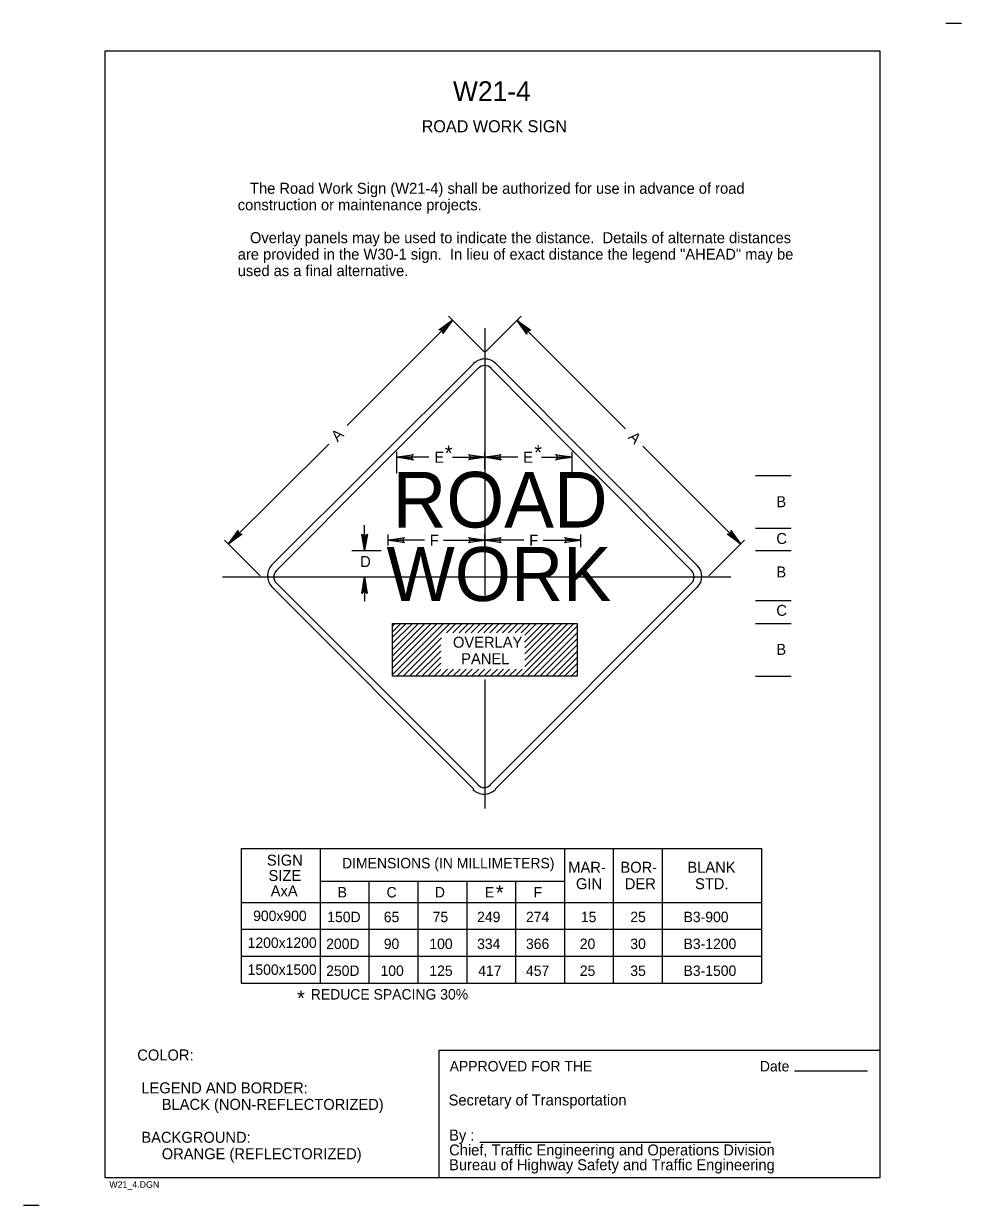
# Model space of a CAD drawing. Extents: x -0.018 to 0.195, y -0.006 to 0.263.
import ezdxf

# ---------------------------------------------------------------- set-up
doc = ezdxf.new("R2010")
doc.units = 0
for name, color, linetype in [('1', 7, 'Continuous'), ('2', 7, 'Continuous'), ('3', 7, 'Continuous')]:
    doc.layers.add(name, color=color, linetype=linetype)

# ---------------------------------------------------------------- blocks, each defined once
blk = doc.blocks.new('RARROW')
at = {"layer": '3'}
for p, q in [((-2.156, 0.28500000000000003), (-2.2665, 0.384625)), ((-2.2665, 0.384625), (0, 0)), ((0, 0), (-2.2665, -0.379125)), ((-2.156, 0.28500000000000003), (-2.075625, 0.12075)), ((0, 0), (-2.156, 0.28500000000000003)), ((-2.14975, -0.2705), (0, 0)), ((-2.075625, 0.12075), (0, 0)), ((0, 0), (-2.074, -0.108)), ((-2.2665, -0.379125), (-2.14975, -0.2705)), ((-2.074, -0.108), (-2.14975, -0.2705))]:
    blk.add_line(p, q, dxfattribs=at)

msp = doc.modelspace()

# ---------------------------------------------------------------- linework, layer by layer
at = {"layer": '1'}
for p, q in [((0.195, 0.26275), (0.1915, 0.26275)), ((0.1765, 0.2565), (0, 0.2565)), ((0, 0.2565), (0, 0)), ((0.1765, 0), (0.1765, 0.2565)), ((0.076, 0.029), (0.1765, 0.029)), ((0.076, 0.029), (0.076, 0)), ((0.157, 0.02425), (0.173625, 0.02425)), ((0.085375, 0.008), (0.151625, 0.008)), ((0, 0), (0.1765, 0)), ((-0.015, -0.0063750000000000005), (-0.0185, -0.0063750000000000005))]:
    msp.add_line(p, q, dxfattribs=at)
at = {"layer": '2'}
msp.add_line((0.1495, 0.074875), (0.1495, 0.0565), dxfattribs=at)
msp.add_line((0.1495, 0.074875), (0.1495, 0.0565), dxfattribs=at)
at = {"layer": '3'}
for p, q in [((0.055125, 0.17125), (0.079125, 0.19525)), ((0.08637500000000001, 0.188), (0.07825, 0.196125)), ((0.08662500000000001, 0.188), (0.09475, 0.196125)), ((0.11850000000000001, 0.1705), (0.093875, 0.195125)), ((0.08650000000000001, 0.193375), (0.08650000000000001, 0.132625)), ((0.038, 0.1395), (0.084, 0.185375)), ((0.039, 0.138125), (0.085, 0.18425)), ((0.08787500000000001, 0.18425), (0.133625, 0.138125)), ((0.089, 0.185375), (0.134875, 0.139375)), ((0.051000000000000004, 0.167), (0.028125, 0.14425)), ((0.0665, 0.160375), (0.0665, 0.16525)), ((0.08650000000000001, 0.16125), (0.08650000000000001, 0.16525)), ((0.106375, 0.16025), (0.106375, 0.16525)), ((0.1225, 0.1665), (0.14475, 0.14425)), ((0.07375, 0.164), (0.0665, 0.164)), ((0.079125, 0.164), (0.08650000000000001, 0.164)), ((0.094, 0.164), (0.08650000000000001, 0.164)), ((0.099375, 0.164), (0.106375, 0.164)), ((0.148125, 0.15987500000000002), (0.15625, 0.15987500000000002)), ((0.059125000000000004, 0.14275000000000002), (0.059125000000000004, 0.1485)), ((0.0645, 0.143875), (0.0645, 0.146375)), ((0.08650000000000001, 0.143125), (0.08650000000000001, 0.146375)), ((0.108375, 0.14350000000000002), (0.108375, 0.146375)), ((0.148125, 0.147875), (0.15625, 0.147875)), ((0.035375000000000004, 0.137), (0.02725, 0.145125)), ((0.05625, 0.14275000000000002), (0.062875, 0.14275000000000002)), ((0.07275, 0.145125), (0.0645, 0.145125)), ((0.077125, 0.145125), (0.08650000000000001, 0.145125)), ((0.095375, 0.145125), (0.08650000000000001, 0.145125)), ((0.09975, 0.145125), (0.108375, 0.145125)), ((0.1375, 0.137), (0.145625, 0.145125)), ((0.148125, 0.14275000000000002), (0.15625, 0.14275000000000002)), ((0.02675, 0.13675), (0.14250000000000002, 0.13675)), ((0.085, 0.089375), (0.039, 0.135375)), ((0.059125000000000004, 0.13675), (0.059125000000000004, 0.13125)), ((0.133625, 0.135375), (0.08775000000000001, 0.089375)), ((0.038, 0.1345), (0.084, 0.088375)), ((0.088875, 0.088375), (0.134875, 0.134375)), ((0.148125, 0.131375), (0.15625, 0.131375)), ((0.0655, 0.123), (0.068625, 0.12612500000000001)), ((0.0655, 0.121625), (0.07, 0.12612500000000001)), ((0.0655, 0.12025), (0.07137500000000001, 0.12612500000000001)), ((0.0655, 0.11875000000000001), (0.072875, 0.12612500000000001)), ((0.0655, 0.11737500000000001), (0.07425, 0.12612500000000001)), ((0.0655, 0.116), (0.075625, 0.12612500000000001)), ((0.0655, 0.1145), (0.077125, 0.12612500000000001)), ((0.0655, 0.12425), (0.067375, 0.12612500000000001)), ((0.0655, 0.1255), (0.066125, 0.12612500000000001)), ((0.0665, 0.114125), (0.0785, 0.12612500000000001)), ((0.07775, 0.124), (0.079875, 0.12612500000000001)), ((0.07925, 0.124), (0.081375, 0.12612500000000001)), ((0.080625, 0.124), (0.08275, 0.12612500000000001)), ((0.082, 0.124), (0.084125, 0.12612500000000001)), ((0.083375, 0.124), (0.0855, 0.12612500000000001)), ((0.084875, 0.124), (0.08700000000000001, 0.12612500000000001)), ((0.08625000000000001, 0.124), (0.088375, 0.12612500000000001)), ((0.08762500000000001, 0.124), (0.08975, 0.12612500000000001)), ((0.089125, 0.124), (0.09125, 0.12612500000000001)), ((0.0905, 0.124), (0.092625, 0.12612500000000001)), ((0.091875, 0.124), (0.094, 0.12612500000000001)), ((0.093375, 0.124), (0.0955, 0.12612500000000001)), ((0.09475, 0.124), (0.096875, 0.12612500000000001)), ((0.0955, 0.121875), (0.09975, 0.12612500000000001)), ((0.095625, 0.120625), (0.101125, 0.12612500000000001)), ((0.095625, 0.11925000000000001), (0.10250000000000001, 0.12612500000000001)), ((0.095625, 0.11775000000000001), (0.10400000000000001, 0.12612500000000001)), ((0.095625, 0.116375), (0.105375, 0.12612500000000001)), ((0.095625, 0.115), (0.10675, 0.12612500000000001)), ((0.095625, 0.1235), (0.09825, 0.12612500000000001)), ((0.096125, 0.114125), (0.1075, 0.1255)), ((0.097625, 0.114125), (0.1075, 0.124)), ((0.148125, 0.12612500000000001), (0.15625, 0.12612500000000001)), ((0.067875, 0.114125), (0.076625, 0.122875)), ((0.069375, 0.114125), (0.0765, 0.12125)), ((0.099, 0.114125), (0.1075, 0.122625)), ((0.100375, 0.114125), (0.1075, 0.12125)), ((0.07075000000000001, 0.114125), (0.0765, 0.11987500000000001)), ((0.072125, 0.114125), (0.0765, 0.11850000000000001)), ((0.10187500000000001, 0.114125), (0.1075, 0.11975000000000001)), ((0.0735, 0.114125), (0.0765, 0.117125)), ((0.076375, 0.114125), (0.078, 0.11575)), ((0.07775, 0.114125), (0.079375, 0.11575)), ((0.07925, 0.114125), (0.080875, 0.11575)), ((0.080625, 0.114125), (0.08225, 0.11575)), ((0.082, 0.114125), (0.083625, 0.11575)), ((0.0835, 0.114125), (0.085125, 0.11575)), ((0.084875, 0.114125), (0.08650000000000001, 0.11575)), ((0.08625000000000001, 0.114125), (0.08787500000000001, 0.11575)), ((0.08775000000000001, 0.114125), (0.089375, 0.11575)), ((0.089125, 0.114125), (0.09075, 0.11575)), ((0.0905, 0.114125), (0.092125, 0.11575)), ((0.092, 0.114125), (0.093625, 0.11575)), ((0.093375, 0.114125), (0.095, 0.11575)), ((0.10325000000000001, 0.114125), (0.1075, 0.11837500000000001)), ((0.104625, 0.114125), (0.1075, 0.117)), ((0.075, 0.114125), (0.0765, 0.115625)), ((0.08650000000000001, 0.113375), (0.08650000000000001, 0.084)), ((0.09475, 0.114125), (0.0955, 0.114875)), ((0.106125, 0.114125), (0.1075, 0.1155)), ((0.148125, 0.114125), (0.15625, 0.114125)), ((0.031, 0.074875), (0.031, 0.04425)), ((0.031, 0.074875), (0.1495, 0.074875)), ((0.049, 0.074875), (0.049, 0.04425)), ((0.104625, 0.067375), (0.049, 0.067375)), ((0.031, 0.062625), (0.1495, 0.062625)), ((0.031, 0.0565), (0.1495, 0.0565)), ((0.031, 0.050375), (0.1495, 0.050375)), ((0.031, 0.04425), (0.1495, 0.04425))]:
    msp.add_line(p, q, dxfattribs=at)
msp.add_lwpolyline([(0.0655, 0.12612500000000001), (0.1075, 0.12612500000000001), (0.1075, 0.114125), (0.0655, 0.114125)], close=True, dxfattribs=at)
for points in [[(0.104625, 0.074875), (0.104625, 0.04425)], [(0.11575, 0.074875), (0.11575, 0.04425)], [(0.12687500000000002, 0.074875), (0.12687500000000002, 0.04425)], [(0.1495, 0.074875), (0.1495, 0.04425)], [(0.1495, 0.074875), (0.1495, 0.0565)], [(0.060125, 0.067375), (0.060125, 0.04425)], [(0.07125000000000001, 0.067375), (0.07125000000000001, 0.04425)], [(0.082375, 0.067375), (0.082375, 0.04425)], [(0.0935, 0.067375), (0.0935, 0.04425)]]:
    msp.add_lwpolyline(points, dxfattribs=at)
for centre, radius, start, end in [((0.08649708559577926, 0.1828493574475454), 0.003535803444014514, 44.92397500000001, 135.85339444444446), ((0.08649708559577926, 0.1828493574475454), 0.0020204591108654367, 44.92397500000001, 135.85339444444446), ((0.040538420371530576, 0.13701110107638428), 0.003535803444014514, 135.70475555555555, 224.93711944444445), ((0.04048239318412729, 0.13674931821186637), 0.00202, 135.04750833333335, 225.00000000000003), ((0.13214328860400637, 0.13675), 0.00202, 315, 45), ((0.13236868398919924, 0.136875), 0.00354, 315, 45), ((0.0863511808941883, 0.09079999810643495), 0.0020204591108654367, 223.5818638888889, 316.1202777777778), ((0.0863511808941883, 0.09079999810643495), 0.0035358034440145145, 223.5818638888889, 316.1202777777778)]:
    msp.add_arc(centre, radius, start, end, dxfattribs=at)

# ---------------------------------------------------------------- block references
for p, xscale, yscale, rotation in [((0.079125, 0.19525), 0.0016545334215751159, 0.0016366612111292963, 45.00000000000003), ((0.093875, 0.195125), 0.001654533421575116, 0.001636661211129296, 135), ((0.0665, 0.164), 0.0016545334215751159, 0.0016366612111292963, 180), ((0.08650000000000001, 0.164), 0.0016545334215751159, 0.0016366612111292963, 180), ((0.028125, 0.14425), 0.0016545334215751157, 0.001636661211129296, -135), ((0.059125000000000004, 0.14275000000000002), 0.0016545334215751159, 0.0016366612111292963, -90), ((0.0645, 0.145125), 0.0016545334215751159, 0.0016366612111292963, 180), ((0.08650000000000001, 0.145125), 0.0016545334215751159, 0.0016366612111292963, 180), ((0.14475, 0.14425), 0.0016545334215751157, 0.001636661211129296, -45), ((0.059125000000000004, 0.13675), 0.0016545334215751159, 0.0016366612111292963, 90)]:
    msp.add_blockref('RARROW', p, dxfattribs=dict(at, xscale=xscale, yscale=yscale, rotation=rotation))
at = {"layer": '3', "xscale": 0.0016545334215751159, "yscale": 0.0016366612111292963}
for p in [(0.08650000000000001, 0.164), (0.106375, 0.164), (0.08650000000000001, 0.145125), (0.108375, 0.145125)]:
    msp.add_blockref('RARROW', p, dxfattribs=at)

# ---------------------------------------------------------------- texts
at = {"layer": '1'}
for s, height, p in [('W21-4', 0.0045000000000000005, (0.07925, 0.245125)), ('ROAD WORK SIGN', 0.00275025, (0.072125, 0.23800000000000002)), ('COLOR:', 0.0024997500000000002, (0.0073750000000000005, 0.026625)), ('APPROVED FOR THE', 0.0023752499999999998, (0.0785, 0.024125)), ('Date ', 0.0023752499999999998, (0.149125, 0.024125)), (' LEGEND AND BORDER:', 0.0024997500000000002, (0.0073750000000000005, 0.019125)), ('Secretary of Transportation', 0.0024997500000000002, (0.07825, 0.016375)), ('      BLACK (NON-REFLECTORIZED)', 0.0024997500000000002, (0.0073750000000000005, 0.015375)), ('By :', 0.0024997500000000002, (0.078375, 0.008375)), (' BACKGROUND:', 0.0024997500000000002, (0.0073750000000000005, 0.007875)), ('      ORANGE (REFLECTORIZED)', 0.0024997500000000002, (0.0073750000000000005, 0.004125)), ('Chief, Traffic Engineering and Operations Division', 0.0024997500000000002, (0.078375, 0.005)), ('Bureau of Highway Safety and Traffic Engineering', 0.0024997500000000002, (0.078375, 0.0016250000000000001)), ('W21_4.DGN', 0.0015, (0.001, -0.002375))]:
    msp.add_text(s, height=height, dxfattribs=at).set_placement(p)
at = {"layer": '2'}
for s, p in [('   The Road Work Sign (W21-4) shall be authorized for use in advance of road ', (0.03025, 0.224)), ('construction or maintenance projects.', (0.03025, 0.22025)), ('   Overlay panels may be used to indicate the distance.  Details of alternate distances ', (0.03025, 0.21275)), ('are provided in the W30-1 sign.  In lieu of exact distance the legend "AHEAD" may be', (0.03025, 0.209)), ('used as a final alternative.', (0.03025, 0.20525000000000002))]:
    msp.add_text(s, height=0.0024997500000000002, dxfattribs=at).set_placement(p)
at = {"layer": '3'}
for rotation, p in [(45, (0.053, 0.167375)), (315, (0.11900000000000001, 0.168375))]:
    msp.add_text('A', height=0.0024997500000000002, rotation=rotation, dxfattribs=at).set_placement(p)
for s, height, p in [('E', 0.0024997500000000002, (0.075, 0.16275)), ('*', 0.00342, (0.077375, 0.16325)), ('E', 0.0024997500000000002, (0.09525, 0.16275)), ('*', 0.00342, (0.09775, 0.163375)), ('ROAD', 0.0126735, (0.0655, 0.148)), ('B', 0.0024997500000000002, (0.152875, 0.152625)), ('F', 0.0024997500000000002, (0.074, 0.143875)), ('F', 0.0024997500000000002, (0.096625, 0.143875)), ('C', 0.0024997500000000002, (0.152875, 0.14425)), ('WORK', 0.012301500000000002, (0.064125, 0.13125)), ('D', 0.0024997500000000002, (0.058125, 0.139)), ('B', 0.0024997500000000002, (0.152875, 0.136625)), ('C', 0.0024997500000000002, (0.152875, 0.12787500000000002)), ('OVERLAY', 0.0024997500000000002, (0.07925, 0.120625)), ('B', 0.0024997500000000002, (0.152875, 0.11900000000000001)), ('PANEL', 0.0024997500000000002, (0.081125, 0.116875)), ('SIGN', 0.0024997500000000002, (0.036875, 0.07100000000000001)), ('DIMENSIONS (IN MILLIMETERS)', 0.0023752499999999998, (0.054, 0.07037500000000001)), ('SIZE', 0.0024997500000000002, (0.03725, 0.0675)), ('MAR-', 0.0024997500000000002, (0.1055, 0.069375)), ('BOR-', 0.0024997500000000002, (0.11737500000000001, 0.069375)), ('BLANK', 0.0024997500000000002, (0.132625, 0.069375)), ('GIN', 0.0024997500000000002, (0.10725, 0.065625)), ('DER', 0.0024997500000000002, (0.11837500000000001, 0.065625)), ('STD.', 0.0024997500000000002, (0.134375, 0.065625)), ('AxA', 0.0024997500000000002, (0.03775, 0.064)), ('B', 0.0023752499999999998, (0.053, 0.06375)), ('C', 0.0023752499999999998, (0.064125, 0.06375)), ('D', 0.0023752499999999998, (0.075125, 0.06375)), ('E', 0.0023752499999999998, (0.08650000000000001, 0.06375)), ('*', 0.00342, (0.089, 0.063125)), ('F', 0.0023752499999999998, (0.097625, 0.06375)), ('900x900', 0.0023752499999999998, (0.03375, 0.058375)), ('150D', 0.0023752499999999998, (0.050625, 0.058125)), ('65', 0.0023752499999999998, (0.0635, 0.058125)), ('75', 0.0023752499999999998, (0.074625, 0.058125)), ('249', 0.0023752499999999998, (0.08475, 0.058125)), ('274', 0.0023752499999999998, (0.095875, 0.058125)), ('15', 0.0023752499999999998, (0.108375, 0.058125)), ('25', 0.0023752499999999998, (0.11962500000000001, 0.058125)), ('B3-900', 0.0023752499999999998, (0.13175, 0.058125)), ('1200x1200', 0.0023752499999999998, (0.0325, 0.05225)), ('200D', 0.0023752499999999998, (0.050375, 0.052000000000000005)), ('90', 0.0023752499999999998, (0.0635, 0.052000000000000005)), ('100', 0.0023752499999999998, (0.073875, 0.052000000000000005)), ('334', 0.0023752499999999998, (0.08475, 0.052000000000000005)), ('366', 0.0023752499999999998, (0.095875, 0.052000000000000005)), ('20', 0.0023752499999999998, (0.108125, 0.052000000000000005)), ('30', 0.0023752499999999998, (0.11962500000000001, 0.052000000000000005)), ('B3-1200', 0.0023752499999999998, (0.13175, 0.052000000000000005)), ('1500x1500', 0.0023752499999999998, (0.0325, 0.046125)), ('250D', 0.0023752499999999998, (0.050375, 0.045875)), ('100', 0.0023752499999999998, (0.06275, 0.045875)), ('125', 0.0023752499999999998, (0.073875, 0.045875)), ('417', 0.0023752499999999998, (0.085, 0.045875)), ('457', 0.0023752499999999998, (0.095875, 0.045875)), ('25', 0.0023752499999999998, (0.108125, 0.045875)), ('35', 0.0023752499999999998, (0.11962500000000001, 0.045875)), ('B3-1500', 0.0023752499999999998, (0.13175, 0.045875)), ('*', 0.00342, (0.043750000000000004, 0.039125)), ('REDUCE SPACING 30%', 0.0023752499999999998, (0.046875, 0.0405))]:
    msp.add_text(s, height=height, dxfattribs=at).set_placement(p)

doc.saveas('drawing.dxf')
